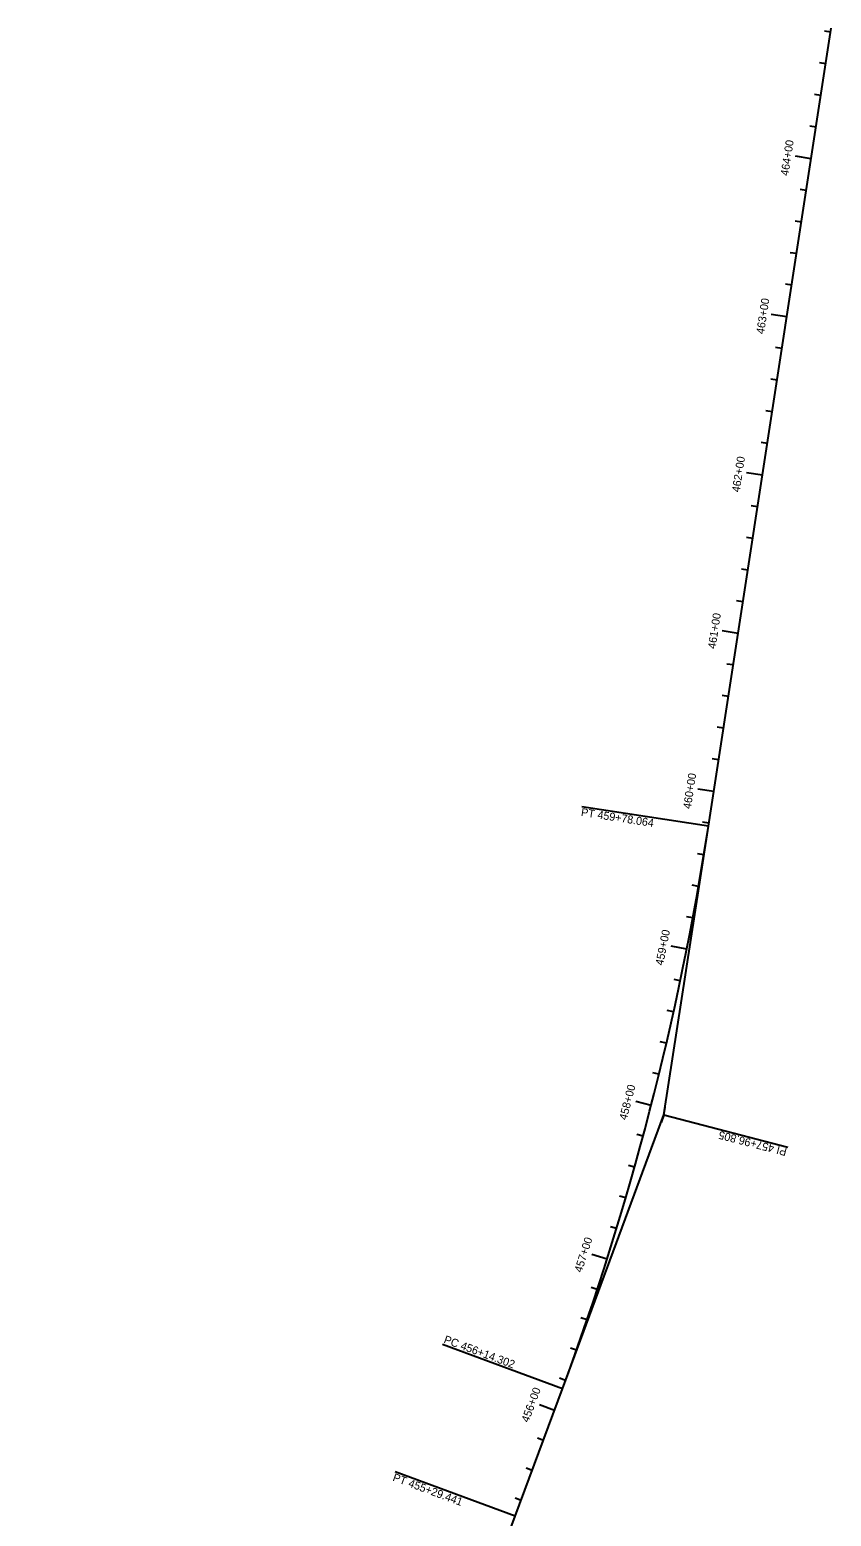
# Model space of a CAD drawing. Extents: x 187748 to 191086, y 249974 to 259749.
# Drawn here: x 189107 to 189608, y 252248 to 253177 of the extents above; entities that cross this region are included whole.
import ezdxf

# ---------------------------------------------------------------- set-up
doc = ezdxf.new("R2010")
doc.units = 0
doc.layers.add('BORDER', color=7, linetype='Continuous')

msp = doc.modelspace()

# ---------------------------------------------------------------- linework, layer by layer
at = {"layer": 'BORDER'}
for p, q in [((189531.24, 252679.28), (189608.07, 253177.79)), ((189607.69, 253175.36), (189603.74, 253175.97)), ((189604.64, 253155.59), (189600.69, 253156.2)), ((189601.6, 253135.83), (189597.65, 253136.43)), ((189598.55, 253116.06), (189594.6, 253116.67)), ((189595.51, 253096.29), (189585.62, 253097.82)), ((189592.46, 253076.53), (189588.51, 253077.13)), ((189589.41, 253056.76), (189585.46, 253057.37)), ((189586.37, 253036.99), (189582.41, 253037.6)), ((189583.32, 253017.23), (189579.37, 253017.83)), ((189580.28, 252997.46), (189570.39, 252998.98)), ((189577.23, 252977.69), (189573.28, 252978.3)), ((189574.18, 252957.93), (189570.23, 252958.53)), ((189571.14, 252938.16), (189567.18, 252938.77)), ((189568.09, 252918.39), (189564.14, 252919)), ((189565.04, 252898.63), (189555.16, 252900.15)), ((189562, 252878.86), (189558.05, 252879.47)), ((189558.95, 252859.09), (189555, 252859.7)), ((189555.91, 252839.33), (189551.95, 252839.93)), ((189552.86, 252819.56), (189548.91, 252820.17)), ((189549.81, 252799.79), (189539.93, 252801.32)), ((189546.77, 252780.03), (189542.81, 252780.63)), ((189543.72, 252760.26), (189539.77, 252760.87)), ((189540.68, 252740.49), (189536.72, 252741.1)), ((189537.63, 252720.73), (189533.68, 252721.33)), ((189534.58, 252700.96), (189524.7, 252702.48)), ((189531.24, 252679.28), (189452.18, 252691.46)), ((189531.54, 252681.19), (189527.58, 252681.8)), ((189528.4, 252661.44), (189524.45, 252662.09)), ((189525.05, 252641.72), (189521.11, 252642.42)), ((189521.47, 252622.04), (189517.54, 252622.78)), ((189517.68, 252602.41), (189507.88, 252604.36)), ((189513.67, 252582.81), (189509.76, 252583.64)), ((189509.45, 252563.27), (189505.54, 252564.13)), ((189505, 252543.77), (189501.11, 252544.68)), ((189500.34, 252524.32), (189496.46, 252525.27)), ((189495.47, 252504.92), (189485.78, 252507.41)), ((189503.45, 252498.91), (189501.71, 252494.22)), ((189503.45, 252498.91), (189504.21, 252503.85)), ((189503.45, 252498.91), (189580.88, 252478.81)), ((189490.38, 252485.58), (189486.51, 252486.62)), ((189485.07, 252466.29), (189481.22, 252467.38)), ((189479.55, 252447.07), (189475.71, 252448.2)), ((189473.82, 252427.91), (189469.99, 252429.08)), ((189467.87, 252408.82), (189458.34, 252411.84)), ((189461.72, 252389.79), (189457.92, 252391.04)), ((189455.35, 252370.83), (189451.56, 252372.12)), ((189440.01, 252327.78), (189365, 252355.59)), ((189448.77, 252351.94), (189445, 252353.28)), ((189410.51, 252248.21), (189440.01, 252327.78)), ((189441.98, 252333.13), (189438.23, 252334.51)), ((189435.04, 252314.37), (189425.66, 252317.85)), ((189428.09, 252295.62), (189424.34, 252297.01)), ((189410.51, 252248.21), (189335.5, 252276.02)), ((189421.14, 252276.87), (189417.39, 252278.26)), ((189414.18, 252258.11), (189410.43, 252259.5))]:
    msp.add_line(p, q, dxfattribs=at)
for points in [[(189440.01, 252327.78), (189503.45, 252498.91), (189531.24, 252679.28)], [(189106.96, 251732.43), (189304.85, 251963.18), (189410.51, 252248.21)]]:
    msp.add_lwpolyline(points, dxfattribs=at)
msp.add_arc((187752.25, 252953.43), 1799.99, 339.66038, 351.23934, dxfattribs=at)

# ---------------------------------------------------------------- texts
for s, rotation, p in [('464+00', 81.2393, (189581.22, 253085.37)), ('463+00', 81.2393, (189565.99, 252986.53)), ('462+00', 81.2393, (189550.76, 252887.69)), ('461+00', 81.2393, (189535.68, 252789.85)), ('460+00', 81.2393, (189520.27, 252689.81)), ('PT 459+78.064', 351.2393, (189451.34, 252685.76)), ('459+00', 78.75444, (189502.91, 252592.04)), ('458+00', 75.57134, (189480.14, 252495.38)), ('PI 457+96.805', 165.44985, (189580.69, 252478.02)), ('457+00', 72.38825, (189452.02, 252400.13)), ('PC 456+14.302', 339.6604, (189365.4, 252356.69)), ('456+00', 69.6604, (189418.78, 252306.45)), ('PT 455+29.441', 339.6604, (189333.47, 252270.55))]:
    msp.add_text(s, height=5, rotation=rotation, dxfattribs=at).set_placement(p)

doc.saveas('drawing.dxf')
